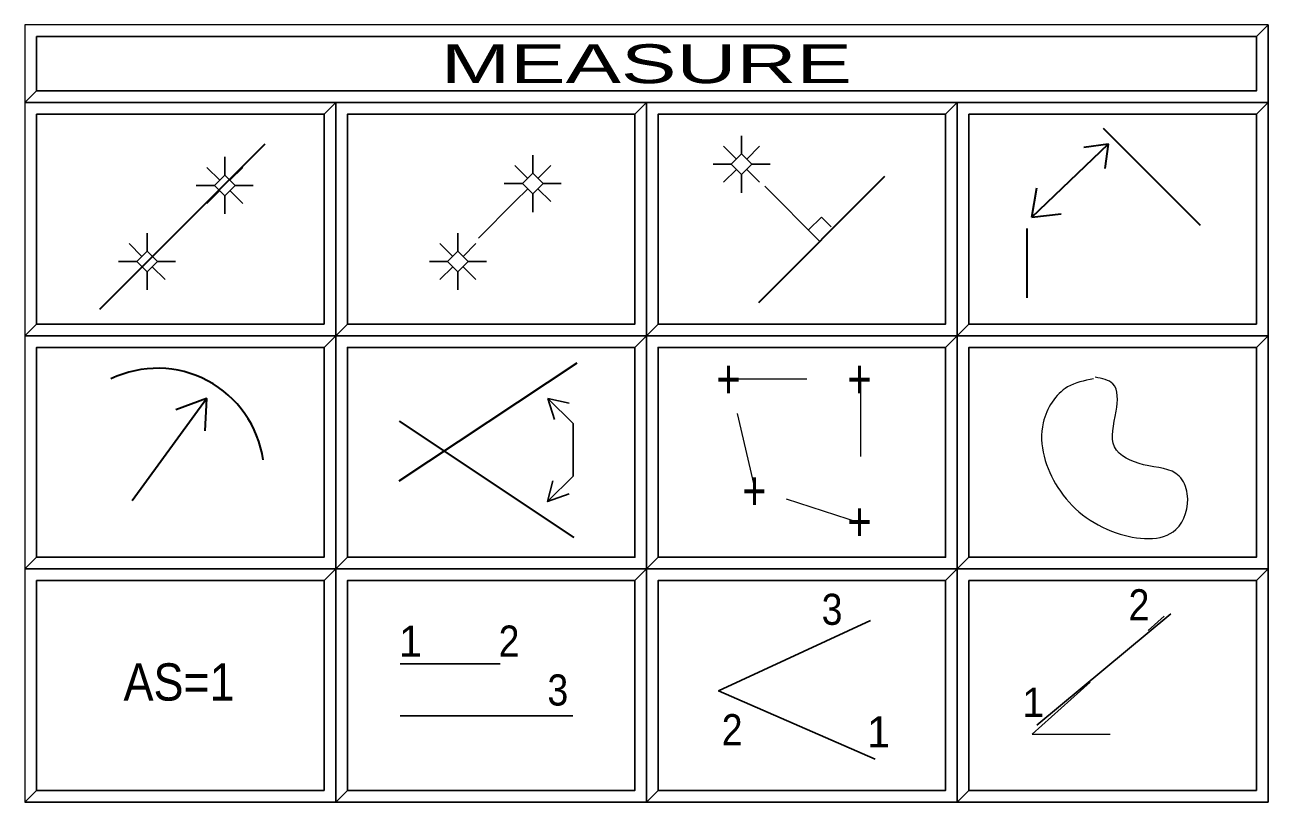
# Model space of a CAD drawing. Extents: x 95906.8 to 95923.6, y 90964.8 to 90972.8.
# Drawn here: x 95910.832 to 95912.432, y 90970.262 to 90971.262 of the extents above; entities that cross this region are included whole.
import ezdxf
from ezdxf.enums import TextEntityAlignment as Align

# ---------------------------------------------------------------- set-up
doc = ezdxf.new("R2010")
doc.units = 0
doc.header["$LTSCALE"] = 0.019
doc.linetypes.add('DOTTED', pattern=[1.5, 0.3, -1.2])
doc.linetypes.add('MEDIUM_DASHED', pattern=[4.5, 3, -1.5])
for name, color, linetype, lineweight in [('11', 7, 'Continuous', 25), ('12', 7, 'Continuous', 25), ('2', 7, 'Continuous', 13), ('21', 7, 'Continuous', 25), ('3', 7, 'Continuous', 25), ('6', 7, 'Continuous', 25)]:
    doc.layers.add(name, color=color, linetype=linetype, lineweight=lineweight)

msp = doc.modelspace()

# ---------------------------------------------------------------- linework, layer by layer
at = {"layer": '11'}
for points in [[(95911.2473, 90970.8767), (95911.6173, 90970.8767), (95911.6173, 90971.1467), (95911.2473, 90971.1467)], [(95911.6473, 90970.8767), (95912.0173, 90970.8767), (95912.0173, 90971.1467), (95911.6473, 90971.1467)], [(95912.0473, 90970.8767), (95912.4173, 90970.8767), (95912.4173, 90971.1467), (95912.0473, 90971.1467)], [(95910.8473, 90970.5767), (95911.2173, 90970.5767), (95911.2173, 90970.8467), (95910.8473, 90970.8467)], [(95911.2473, 90970.5767), (95911.6173, 90970.5767), (95911.6173, 90970.8467), (95911.2473, 90970.8467)], [(95911.6473, 90970.5767), (95912.0173, 90970.5767), (95912.0173, 90970.8467), (95911.6473, 90970.8467)], [(95912.0473, 90970.5767), (95912.4173, 90970.5767), (95912.4173, 90970.8467), (95912.0473, 90970.8467)], [(95910.8473, 90970.2767), (95911.2173, 90970.2767), (95911.2173, 90970.5467), (95910.8473, 90970.5467)], [(95911.2473, 90970.2767), (95911.6173, 90970.2767), (95911.6173, 90970.5467), (95911.2473, 90970.5467)], [(95911.6473, 90970.2767), (95912.0173, 90970.2767), (95912.0173, 90970.5467), (95911.6473, 90970.5467)], [(95912.0473, 90970.2767), (95912.4173, 90970.2767), (95912.4173, 90970.5467), (95912.0473, 90970.5467)]]:
    msp.add_lwpolyline(points, close=True, dxfattribs=at)
at = {"layer": '12'}
msp.add_lwpolyline([(95910.8473, 90970.8767), (95911.2173, 90970.8767), (95911.2173, 90971.1467), (95910.8473, 90971.1467)], close=True, dxfattribs=at)
at = {"layer": '2'}
for points in [[(95910.8323, 90971.2617), (95910.8323, 90971.1617), (95910.8473, 90971.1767), (95910.8473, 90971.2467), (95912.4173, 90971.2467), (95912.4323, 90971.2617)], [(95910.8323, 90971.1617), (95910.8323, 90970.8617), (95910.8473, 90970.8767), (95910.8473, 90971.1467), (95911.2173, 90971.1467), (95911.2323, 90971.1617)], [(95911.2323, 90971.1617), (95911.2323, 90970.8617), (95911.2473, 90970.8767), (95911.2473, 90971.1467), (95911.6173, 90971.1467), (95911.6323, 90971.1617)], [(95911.6323, 90971.1617), (95911.6323, 90970.8617), (95911.6473, 90970.8767), (95911.6473, 90971.1467), (95912.0173, 90971.1467), (95912.0323, 90971.1617)], [(95912.0323, 90971.1617), (95912.0323, 90970.8617), (95912.0473, 90970.8767), (95912.0473, 90971.1467), (95912.4173, 90971.1467), (95912.4323, 90971.1617)], [(95910.8323, 90970.8617), (95910.8323, 90970.5617), (95910.8473, 90970.5767), (95910.8473, 90970.8467), (95911.2173, 90970.8467), (95911.2323, 90970.8617)], [(95911.2323, 90970.8617), (95911.2323, 90970.5617), (95911.2473, 90970.5767), (95911.2473, 90970.8467), (95911.6173, 90970.8467), (95911.6323, 90970.8617)], [(95911.6323, 90970.8617), (95911.6323, 90970.5617), (95911.6473, 90970.5767), (95911.6473, 90970.8467), (95912.0173, 90970.8467), (95912.0323, 90970.8617)], [(95912.0323, 90970.8617), (95912.0323, 90970.5617), (95912.0473, 90970.5767), (95912.0473, 90970.8467), (95912.4173, 90970.8467), (95912.4323, 90970.8617)], [(95910.8323, 90970.5617), (95910.8323, 90970.2617), (95910.8473, 90970.2767), (95910.8473, 90970.5467), (95911.2173, 90970.5467), (95911.2323, 90970.5617)], [(95911.2323, 90970.5617), (95911.2323, 90970.2617), (95911.2473, 90970.2767), (95911.2473, 90970.5467), (95911.6173, 90970.5467), (95911.6323, 90970.5617)], [(95911.6323, 90970.5617), (95911.6323, 90970.2617), (95911.6473, 90970.2767), (95911.6473, 90970.5467), (95912.0173, 90970.5467), (95912.0323, 90970.5617)], [(95912.0323, 90970.5617), (95912.0323, 90970.2617), (95912.0473, 90970.2767), (95912.0473, 90970.5467), (95912.4173, 90970.5467), (95912.4323, 90970.5617)]]:
    msp.add_lwpolyline(points, close=True, dxfattribs=at)
at = {"layer": '21'}
msp.add_lwpolyline([(95910.8473, 90971.1767), (95912.4173, 90971.1767), (95912.4173, 90971.2467), (95910.8473, 90971.2467)], close=True, dxfattribs=at)
at = {"layer": '3'}
for points in [[(95910.8323, 90971.1617), (95912.4323, 90971.1617), (95912.4323, 90971.2617), (95912.4173, 90971.2467), (95912.4173, 90971.1767), (95910.8473, 90971.1767)], [(95910.8323, 90970.8617), (95911.2323, 90970.8617), (95911.2323, 90971.1617), (95911.2173, 90971.1467), (95911.2173, 90970.8767), (95910.8473, 90970.8767)], [(95911.2323, 90970.8617), (95911.6323, 90970.8617), (95911.6323, 90971.1617), (95911.6173, 90971.1467), (95911.6173, 90970.8767), (95911.2473, 90970.8767)], [(95911.6323, 90970.8617), (95912.0323, 90970.8617), (95912.0323, 90971.1617), (95912.0173, 90971.1467), (95912.0173, 90970.8767), (95911.6473, 90970.8767)], [(95912.0323, 90970.8617), (95912.4323, 90970.8617), (95912.4323, 90971.1617), (95912.4173, 90971.1467), (95912.4173, 90970.8767), (95912.0473, 90970.8767)], [(95910.8323, 90970.5617), (95911.2323, 90970.5617), (95911.2323, 90970.8617), (95911.2173, 90970.8467), (95911.2173, 90970.5767), (95910.8473, 90970.5767)], [(95911.2323, 90970.5617), (95911.6323, 90970.5617), (95911.6323, 90970.8617), (95911.6173, 90970.8467), (95911.6173, 90970.5767), (95911.2473, 90970.5767)], [(95911.6323, 90970.5617), (95912.0323, 90970.5617), (95912.0323, 90970.8617), (95912.0173, 90970.8467), (95912.0173, 90970.5767), (95911.6473, 90970.5767)], [(95912.0323, 90970.5617), (95912.4323, 90970.5617), (95912.4323, 90970.8617), (95912.4173, 90970.8467), (95912.4173, 90970.5767), (95912.0473, 90970.5767)], [(95910.8323, 90970.2617), (95911.2323, 90970.2617), (95911.2323, 90970.5617), (95911.2173, 90970.5467), (95911.2173, 90970.2767), (95910.8473, 90970.2767)], [(95911.2323, 90970.2617), (95911.6323, 90970.2617), (95911.6323, 90970.5617), (95911.6173, 90970.5467), (95911.6173, 90970.2767), (95911.2473, 90970.2767)], [(95911.6323, 90970.2617), (95912.0323, 90970.2617), (95912.0323, 90970.5617), (95912.0173, 90970.5467), (95912.0173, 90970.2767), (95911.6473, 90970.2767)], [(95912.0323, 90970.2617), (95912.4323, 90970.2617), (95912.4323, 90970.5617), (95912.4173, 90970.5467), (95912.4173, 90970.2767), (95912.0473, 90970.2767)]]:
    msp.add_lwpolyline(points, close=True, dxfattribs=at)
at = {"layer": '6', "lineweight": 35}
for p, q in [((95912.22, 90971.129), (95912.3449, 90971.004)), ((95911.141, 90971.1082), (95910.9285, 90970.8957)), ((95912.2263, 90971.1082), (95912.195, 90971.104)), ((95911.9387, 90971.0665), (95911.7763, 90970.9041)), ((95912.1284, 90971.0145), (95912.1346, 90971.052)), ((95912.1284, 90971.0145), (95912.1659, 90971.0186)), ((95912.1221, 90970.9103), (95912.1221, 90970.9999)), ((95911.3139, 90970.6749), (95911.543, 90970.827)), ((95911.066, 90970.7812), (95911.0264, 90970.7666)), ((95911.3139, 90970.752), (95911.5389, 90970.602))]:
    msp.add_line(p, q, dxfattribs=at)
at = {"layer": '6', "linetype": 'MEDIUM_DASHED', "lineweight": 13}
for p, q in [((95911.7481, 90971.089), (95911.7315, 90971.1056)), ((95911.7481, 90971.089), (95911.7315, 90971.1056)), ((95911.7613, 90971.089), (95911.7779, 90971.1056)), ((95911.7613, 90971.089), (95911.7779, 90971.1056)), ((95911.083, 90971.0617), (95911.0664, 90971.0783)), ((95911.083, 90971.0617), (95911.0664, 90971.0783)), ((95911.0962, 90971.0617), (95911.1128, 90971.0783)), ((95911.0962, 90971.0617), (95911.1128, 90971.0783)), ((95911.4794, 90971.064), (95911.4628, 90971.0806)), ((95911.4794, 90971.064), (95911.4628, 90971.0806)), ((95911.4926, 90971.064), (95911.5092, 90971.0806)), ((95911.4926, 90971.064), (95911.5092, 90971.0806)), ((95911.7481, 90971.0758), (95911.7315, 90971.0593)), ((95911.7481, 90971.0758), (95911.7315, 90971.0593)), ((95911.7613, 90971.0758), (95911.7779, 90971.0593)), ((95911.7613, 90971.0758), (95911.7779, 90971.0593)), ((95911.083, 90971.0485), (95911.0664, 90971.032)), ((95911.083, 90971.0485), (95911.0664, 90971.032)), ((95911.0962, 90971.0485), (95911.1128, 90971.032)), ((95911.0962, 90971.0485), (95911.1128, 90971.032)), ((95911.4794, 90971.0508), (95911.4628, 90971.0343)), ((95911.4794, 90971.0508), (95911.4628, 90971.0343)), ((95911.4926, 90971.0508), (95911.5092, 90971.0343)), ((95911.4926, 90971.0508), (95911.5092, 90971.0343)), ((95910.983, 90970.9638), (95910.9664, 90970.9804)), ((95910.983, 90970.9638), (95910.9664, 90970.9804)), ((95910.9962, 90970.9638), (95911.0128, 90970.9804)), ((95910.9962, 90970.9638), (95911.0128, 90970.9804)), ((95911.383, 90970.9638), (95911.3664, 90970.9804)), ((95911.383, 90970.9638), (95911.3664, 90970.9804)), ((95911.3962, 90970.9638), (95911.4128, 90970.9804)), ((95911.3962, 90970.9638), (95911.4128, 90970.9804)), ((95910.983, 90970.9506), (95910.9664, 90970.9341)), ((95910.983, 90970.9506), (95910.9664, 90970.9341)), ((95910.9962, 90970.9506), (95911.0128, 90970.9341)), ((95910.9962, 90970.9506), (95911.0128, 90970.9341)), ((95911.383, 90970.9506), (95911.3664, 90970.9341)), ((95911.383, 90970.9506), (95911.3664, 90970.9341)), ((95911.3962, 90970.9506), (95911.4128, 90970.9341)), ((95911.3962, 90970.9506), (95911.4128, 90970.9341)), ((95912.1288, 90970.3492), (95912.2983, 90970.5011)), ((95912.1288, 90970.3492), (95912.3187, 90970.3492))]:
    msp.add_line(p, q, dxfattribs=at)
at = {"layer": '6'}
for p, q in [((95911.7547, 90971.0957), (95911.7547, 90971.1191)), ((95911.7547, 90971.0957), (95911.7547, 90971.1191)), ((95911.0896, 90971.0684), (95911.0896, 90971.0918)), ((95911.0896, 90971.0684), (95911.0896, 90971.0918)), ((95911.486, 90971.0707), (95911.486, 90971.0941)), ((95911.486, 90971.0707), (95911.486, 90971.0941)), ((95911.7415, 90971.0824), (95911.718, 90971.0824)), ((95911.7679, 90971.0824), (95911.7913, 90971.0824)), ((95911.7679, 90971.0824), (95911.7913, 90971.0824)), ((95911.4728, 90971.0574), (95911.4493, 90971.0574)), ((95911.4992, 90971.0574), (95911.5226, 90971.0574)), ((95911.4992, 90971.0574), (95911.5226, 90971.0574)), ((95911.7547, 90971.0692), (95911.7547, 90971.0458)), ((95911.7547, 90971.0692), (95911.7547, 90971.0458)), ((95911.0764, 90971.0551), (95911.0529, 90971.0551)), ((95911.0896, 90971.0419), (95911.0896, 90971.0185)), ((95911.0896, 90971.0419), (95911.0896, 90971.0185)), ((95911.1028, 90971.0551), (95911.1262, 90971.0551)), ((95911.1028, 90971.0551), (95911.1262, 90971.0551)), ((95911.486, 90971.0442), (95911.486, 90971.0208)), ((95911.486, 90971.0442), (95911.486, 90971.0208)), ((95911.7846, 90971.054), (95911.8554, 90970.9832)), ((95910.9896, 90970.9705), (95910.9896, 90970.9939)), ((95910.9896, 90970.9705), (95910.9896, 90970.9939)), ((95911.3896, 90970.9705), (95911.3896, 90970.9939)), ((95911.3896, 90970.9705), (95911.3896, 90970.9939)), ((95910.9764, 90970.9572), (95910.9529, 90970.9572)), ((95911.0028, 90970.9572), (95911.0262, 90970.9572)), ((95911.0028, 90970.9572), (95911.0262, 90970.9572)), ((95911.3764, 90970.9572), (95911.3529, 90970.9572)), ((95911.4028, 90970.9572), (95911.4262, 90970.9572)), ((95911.4028, 90970.9572), (95911.4262, 90970.9572)), ((95910.9896, 90970.944), (95910.9896, 90970.9206)), ((95910.9896, 90970.944), (95910.9896, 90970.9206)), ((95911.3896, 90970.944), (95911.3896, 90970.9206)), ((95911.3896, 90970.944), (95911.3896, 90970.9206)), ((95911.5055, 90970.7812), (95911.5139, 90970.7541)), ((95911.5055, 90970.7812), (95911.5326, 90970.7749)), ((95911.505, 90970.6484), (95911.5118, 90970.6749)), ((95912.1347, 90970.3609), (95912.307, 90970.504)), ((95911.3153, 90970.4398), (95911.4439, 90970.4398)), ((95911.3153, 90970.3726), (95911.5373, 90970.3726))]:
    msp.add_line(p, q, dxfattribs=at)
at = {"layer": '6', "linetype": 'DOTTED', "lineweight": 13}
msp.add_line((95911.4159, 90970.9874), (95911.4628, 90971.0343), dxfattribs=at)
at = {"layer": '6', "lineweight": 35}
for points in [[(95912.1284, 90971.0145), (95912.2263, 90971.1082), (95912.2221, 90971.077)], [(95910.9702, 90970.6499), (95911.066, 90970.7812), (95911.0639, 90970.7395)]]:
    msp.add_lwpolyline(points, dxfattribs=at)
at = {"layer": '6', "lineweight": 13}
for points in [[(95911.7547, 90971.0692), (95911.768, 90971.0825), (95911.7547, 90971.0957), (95911.7414, 90971.0825)], [(95911.7547, 90971.0692), (95911.768, 90971.0825), (95911.7547, 90971.0957), (95911.7414, 90971.0825)], [(95911.0896, 90971.0419), (95911.1029, 90971.0552), (95911.0896, 90971.0684), (95911.0763, 90971.0552)], [(95911.0896, 90971.0419), (95911.1029, 90971.0552), (95911.0896, 90971.0684), (95911.0763, 90971.0552)], [(95911.486, 90971.0442), (95911.4993, 90971.0575), (95911.486, 90971.0707), (95911.4727, 90971.0575)], [(95911.486, 90971.0442), (95911.4993, 90971.0575), (95911.486, 90971.0707), (95911.4727, 90971.0575)], [(95910.9896, 90970.944), (95911.0029, 90970.9573), (95910.9896, 90970.9705), (95910.9763, 90970.9573)], [(95910.9896, 90970.944), (95911.0029, 90970.9573), (95910.9896, 90970.9705), (95910.9763, 90970.9573)], [(95911.3896, 90970.944), (95911.4029, 90970.9573), (95911.3896, 90970.9705), (95911.3763, 90970.9573)], [(95911.3896, 90970.944), (95911.4029, 90970.9573), (95911.3896, 90970.9705), (95911.3763, 90970.9573)]]:
    msp.add_lwpolyline(points, close=True, dxfattribs=at)
msp.add_lwpolyline([(95911.8409, 90970.9978), (95911.8576, 90971.0145), (95911.87, 90971.002)], dxfattribs=at)
at = {"layer": '6', "linetype": 'MEDIUM_DASHED', "lineweight": 13}
msp.add_lwpolyline([(95911.7388, 90970.8062), (95911.9076, 90970.8062), (95911.9076, 90970.6208), (95911.7722, 90970.6645)], close=True, dxfattribs=at)
at = {"layer": '6'}
for points in [[(95911.5055, 90970.7812), (95911.5378, 90970.7488), (95911.5378, 90970.6812), (95911.505, 90970.6484), (95911.5326, 90970.6583)], [(95911.9207, 90970.4953), (95911.725, 90970.4047), (95911.9266, 90970.3171)]]:
    msp.add_lwpolyline(points, dxfattribs=at)
at = {"layer": '6', "lineweight": 35}
msp.add_arc((95911.0029, 90970.6825), 0.1374, 8.167, 115.7914, dxfattribs=at)
at = {"layer": '6', "lineweight": 13}
msp.add_spline([(95912.2075, 90970.8062), (95912.1742, 90970.7958), (95912.1429, 90970.7499), (95912.1617, 90970.6666), (95912.2367, 90970.6083), (95912.3137, 90970.6125), (95912.3283, 90970.6583), (95912.3179, 90970.6812), (95912.2721, 90970.6958), (95912.2346, 90970.7187), (95912.2367, 90970.7645), (95912.2325, 90970.7999), (95912.2096, 90970.8083)], degree=3, dxfattribs=at)

# ---------------------------------------------------------------- texts
at = {"layer": '21', "width": 1.6}
msp.add_text('        MEASURE        ', height=0.04999, dxfattribs=at).set_placement((95911.6322, 90971.1867), align=Align.CENTER)
at = {"layer": '6', "width": 0.8}
for p in [(95911.7222, 90970.7812), (95911.8909, 90970.7812), (95911.7555, 90970.6375), (95911.8909, 90970.5979)]:
    msp.add_text('+', height=0.05, dxfattribs=at).set_placement(p)
at = {"layer": '6', "width": 0.9}
for s, height, p in [('3', 0.04, (95911.8711, 90970.4898)), ('2', 0.04, (95912.2661, 90970.4956)), ('2', 0.04, (95911.4554, 90970.4489)), ('AS=1', 0.048, (95911.0308, 90970.3923)), ('3', 0.04, (95911.5182, 90970.386)), ('2', 0.04, (95911.7425, 90970.3349))]:
    msp.add_text(s, height=height, dxfattribs=at).set_placement(p, align=Align.CENTER)
at = {"layer": '6'}
for height, p in [(0.04, (95911.3286, 90970.4489)), (0.0375, (95912.13, 90970.3713)), (0.04, (95911.931, 90970.332))]:
    msp.add_text('1', height=height, dxfattribs=at).set_placement(p, align=Align.CENTER)

doc.saveas('drawing.dxf')
